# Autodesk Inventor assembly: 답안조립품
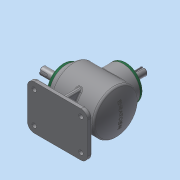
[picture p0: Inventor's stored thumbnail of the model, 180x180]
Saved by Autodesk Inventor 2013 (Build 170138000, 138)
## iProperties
Created: 2016-09
Part Number: 답안조립품
Document SubType Name: Assembly
Designer: dgall
Author: dgall
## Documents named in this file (14)
- C:\Users\dgall\Desktop\460907V1011\답안조립품.iam
- C:\Users\dgall\Desktop\460907V1011\본체.ipt
- C:\Users\dgall\Desktop\460907V1011\메인 베벨기어.ipt
- C:\Users\dgall\Desktop\460907V1011\메인 축.ipt
- 메인 축.ipt
- C:\Users\dgall\Desktop\460907V1011\베어링 6203.ipt
- C:\Users\dgall\Desktop\460907V1011\서브 베벨기어.ipt
- C:\Users\dgall\Desktop\460907V1011\서브 축.ipt
- 서브 축.ipt
- C:\Users\dgall\Desktop\460907V1011\키 4x4.ipt
- C:\Users\dgall\Desktop\460907V1011\키 5x5.ipt
- C:\Users\dgall\Desktop\460907V1011\M4.ipt
- C:\Users\dgall\Desktop\460907V1011\오일실 17 32 8.ipt
- C:\Users\dgall\Desktop\460907V1011\커버.ipt
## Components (8 placed, 1 different names)
1. M4:1
2. M4:3
3. M4:4
4. M4:5
5. M4:2
6. M4:6
7. M4:7
8. M4:8
